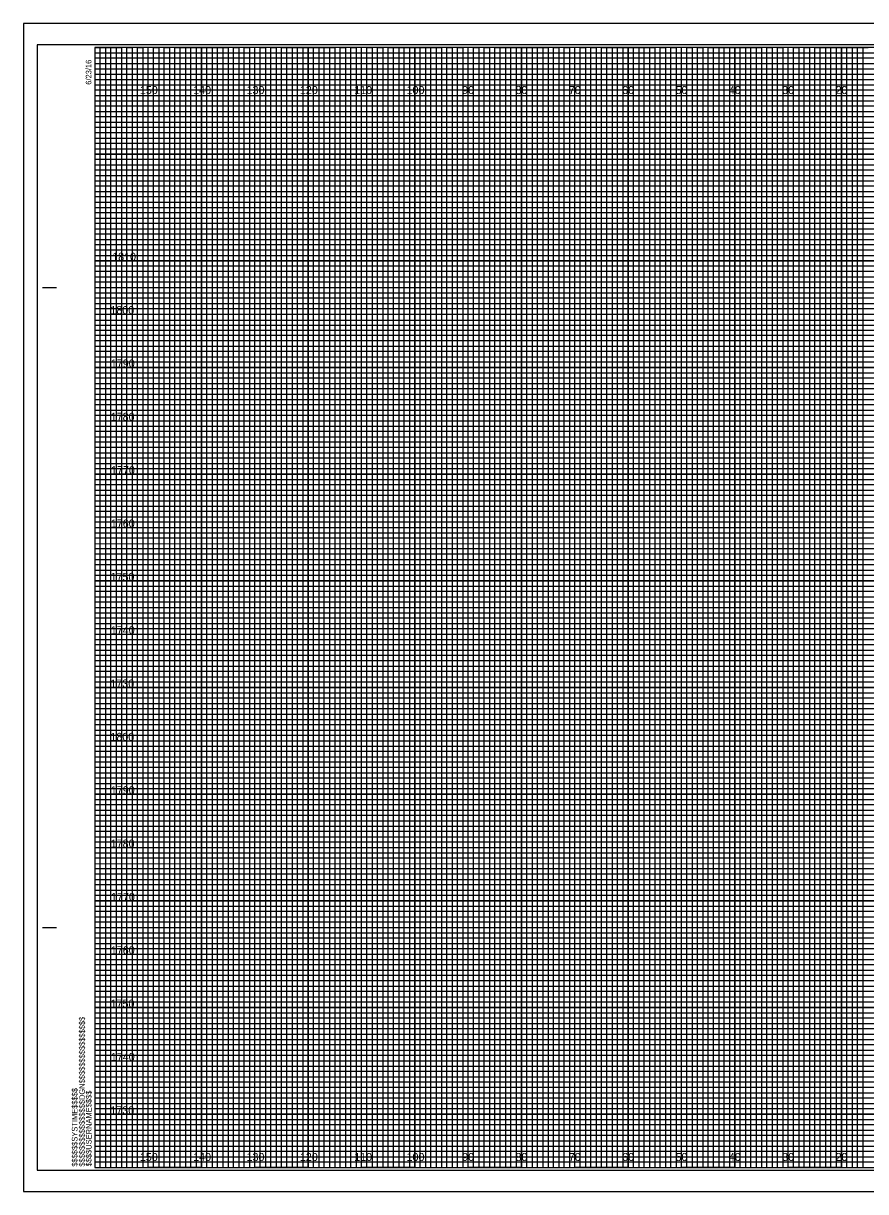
# Model space of a CAD drawing. Extents: x -419 to 4739, y -630 to 13534.
# Drawn here: x 476.2 to 634.1, y 428 to 647 of the extents above; entities that cross this region are included whole.
import ezdxf

# ---------------------------------------------------------------- set-up
doc = ezdxf.new("R2010")
doc.units = 0
for name, color, linetype in [('Old_Level_62', 7, 'Continuous'), ('Pattern 1', 7, 'Continuous'), ('Pattern 18', 7, 'Continuous'), ('Pattern 4', 7, 'Continuous'), ('Pattern 5', 7, 'Continuous'), ('Prop Dimension', 7, 'Continuous'), ('Prop Horizontal Alignment', 7, 'Continuous'), ('Raster_Level_0', 7, 'Continuous'), ('Scratch_Level_0', 7, 'Continuous'), ('Scratch_Level_3', 7, 'Continuous'), ('Scratch_Level_5', 7, 'Continuous')]:
    doc.layers.add(name, color=color, linetype=linetype)

msp = doc.modelspace()

# ---------------------------------------------------------------- linework, layer by layer
at = {"layer": 'Old_Level_62'}
for p, q in [((479.78, 597.54), (482.28, 597.54)), ((479.88, 597.54), (482.38, 597.54)), ((479.78, 477.54), (482.28, 477.54)), ((479.88, 477.54), (482.38, 477.54)), ((489.58, 432.54), (489.58, 432.54)), ((489.58, 432.54), (489.58, 432.54)), ((489.58, 432.54), (489.58, 432.54)), ((489.58, 432.54), (489.58, 432.54)), ((489.58, 432.54), (489.58, 432.54)), ((489.58, 432.54), (489.58, 432.54)), ((489.58, 432.54), (489.58, 432.54))]:
    msp.add_line(p, q, dxfattribs=at)
msp.add_lwpolyline([(809.58, 642.54), (489.58, 642.54), (489.58, 432.54), (809.58, 432.54)], close=True, dxfattribs=at)
at = {"layer": 'Pattern 18'}
msp.add_lwpolyline([(476.18, 428.04), (812.88, 428.04), (812.88, 647.04), (476.18, 647.04)], close=True, dxfattribs=at)
at = {"layer": 'Pattern 4'}
for p, q in [((489.58, 641.54), (749.58, 641.54)), ((749.58, 640.52), (489.58, 640.52)), ((489.58, 640.52), (489.58, 639.54)), ((489.58, 639.54), (749.58, 639.54)), ((749.58, 638.43), (489.58, 638.43)), ((489.58, 638.43), (489.58, 636.54)), ((489.58, 636.54), (809.58, 636.54))]:
    msp.add_line(p, q, dxfattribs=at)
for points in [[(489.58, 635.54), (759.58, 635.54), (809.58, 635.54), (809.58, 634.54), (489.58, 634.54)], [(489.58, 633.54), (809.58, 633.54), (809.58, 631.54), (489.58, 631.54)], [(489.58, 630.54), (809.58, 630.54), (809.58, 629.54), (489.58, 629.52)], [(489.58, 628.54), (809.58, 628.54), (809.58, 626.54), (489.58, 626.54)], [(489.58, 625.54), (809.58, 625.54), (809.58, 624.54), (489.58, 624.54)], [(489.58, 623.54), (809.58, 623.54), (809.58, 621.54), (489.58, 621.54)], [(489.58, 620.54), (809.58, 620.54), (809.58, 619.54), (489.58, 619.54)], [(489.58, 618.54), (809.58, 618.54), (809.58, 616.54), (489.58, 616.54)], [(489.58, 615.54), (809.58, 615.54), (809.58, 614.54), (489.58, 614.54)], [(489.58, 613.54), (809.58, 613.54), (809.58, 611.54), (489.58, 611.54)], [(489.58, 610.54), (809.58, 610.54), (809.58, 609.54), (489.58, 609.54)], [(489.58, 608.54), (809.58, 608.54), (809.58, 606.49), (809.58, 605.54), (809.58, 604.54), (489.58, 604.54)], [(489.58, 606.54), (809.58, 606.54), (809.58, 605.54), (489.58, 605.54)], [(489.58, 603.54), (809.58, 603.54), (809.58, 601.54), (489.58, 601.57)], [(489.58, 601.57), (809.58, 601.54), (809.58, 600.54), (489.58, 600.54)], [(489.58, 599.54), (809.58, 599.54), (809.58, 598.54), (489.58, 598.54)], [(489.58, 596.54), (809.58, 596.54), (809.58, 595.54), (489.58, 595.54)], [(489.58, 594.54), (809.58, 594.54), (809.58, 593.54), (489.58, 593.54)], [(489.51, 591.43), (809.58, 591.43), (809.58, 590.42), (489.51, 590.42)], [(489.58, 589.54), (809.58, 589.54), (809.58, 588.54), (489.58, 588.54)], [(489.58, 586.54), (809.58, 586.54), (809.58, 585.54), (489.58, 585.54)], [(489.58, 584.54), (809.58, 584.54), (809.58, 583.54), (489.58, 583.54)], [(489.58, 581.54), (809.58, 581.54), (809.58, 580.54), (489.58, 580.54)], [(489.58, 579.54), (809.58, 579.54), (809.58, 578.54), (489.58, 578.54)], [(489.58, 576.54), (809.58, 576.54), (809.58, 575.54), (489.58, 575.54)], [(489.58, 574.54), (809.58, 574.54), (809.58, 573.54), (489.58, 573.54)], [(489.58, 571.54), (809.58, 571.54), (809.57, 570.52), (489.58, 570.54)], [(489.58, 569.54), (809.58, 569.54), (809.58, 568.54), (489.58, 568.54)], [(489.58, 566.54), (809.58, 566.54), (809.58, 565.54), (489.58, 565.54)], [(489.58, 564.54), (809.58, 564.54), (809.58, 563.54), (489.58, 563.54)], [(489.58, 561.54), (809.58, 561.54), (809.58, 560.54), (489.58, 560.54)], [(489.58, 559.54), (809.58, 559.54), (809.58, 558.54), (489.58, 558.54)], [(489.58, 556.54), (809.58, 556.54), (809.58, 555.54), (489.58, 555.54)], [(489.58, 554.54), (809.58, 554.54), (809.58, 553.54), (489.58, 553.54)], [(489.58, 551.54), (809.58, 551.54), (809.58, 550.54), (489.58, 550.54)], [(489.58, 549.53), (809.65, 549.45), (809.58, 548.54), (489.58, 548.54)], [(489.58, 546.54), (809.58, 546.54), (809.58, 545.54), (489.58, 545.54)], [(489.58, 544.54), (809.58, 544.54), (809.58, 543.54), (489.58, 543.54)], [(489.58, 541.54), (809.58, 541.54), (809.58, 540.54), (489.58, 540.54)], [(489.58, 539.54), (809.58, 539.54), (809.58, 538.54), (489.58, 538.54)], [(489.58, 536.54), (809.58, 536.54), (809.58, 535.54), (489.58, 535.54)], [(489.58, 534.54), (809.58, 534.54), (809.58, 533.54), (489.58, 533.54)], [(489.58, 531.54), (809.58, 531.54), (809.58, 530.54), (489.58, 530.54)], [(489.58, 529.54), (809.58, 529.54), (809.58, 528.54), (489.58, 528.54)], [(489.58, 526.54), (809.58, 526.54), (809.58, 525.54), (489.58, 525.54)], [(489.58, 524.54), (809.58, 524.54), (809.58, 523.54), (489.58, 523.54)], [(489.58, 521.54), (809.58, 521.54), (809.58, 520.54), (489.58, 520.54)], [(489.58, 519.54), (809.58, 519.54), (809.58, 518.54), (489.58, 518.54)], [(489.58, 516.54), (809.58, 516.54), (809.58, 515.54), (489.58, 515.54)], [(489.58, 514.54), (809.58, 514.54), (809.58, 513.54), (489.58, 513.54)], [(489.58, 511.54), (809.58, 511.54), (809.57, 510.52), (489.58, 510.54)], [(489.58, 509.54), (809.58, 509.54), (809.58, 508.54), (489.58, 508.54)], [(489.58, 506.54), (809.58, 506.54), (809.58, 505.54), (489.58, 505.54)], [(489.58, 504.54), (809.58, 504.54), (809.58, 503.54), (489.58, 503.54)], [(489.58, 501.54), (809.58, 501.54), (809.58, 500.54), (489.58, 500.54)], [(489.58, 499.54), (809.58, 499.54), (809.58, 498.54), (489.58, 498.54)], [(489.58, 496.54), (809.58, 496.54), (809.58, 495.54), (489.58, 495.54)], [(489.58, 494.54), (809.58, 494.54), (809.58, 493.54), (489.58, 493.54)], [(489.58, 491.54), (809.58, 491.54), (809.58, 490.54), (489.58, 490.54)], [(489.58, 489.53), (809.65, 489.45), (809.58, 488.54), (489.58, 488.54)], [(489.58, 486.54), (809.58, 486.54), (809.58, 485.54), (489.58, 485.54)], [(489.58, 484.54), (809.58, 484.54), (809.58, 483.54), (489.58, 483.54)], [(489.58, 481.54), (809.58, 481.54), (809.58, 480.54), (489.58, 480.54)], [(489.58, 479.54), (809.58, 479.54), (809.58, 478.54), (489.58, 478.54)], [(489.58, 476.54), (809.58, 476.54), (809.58, 475.54), (489.58, 475.54)], [(489.58, 474.54), (809.58, 474.54), (809.58, 473.54), (489.58, 473.54)], [(489.58, 471.54), (809.58, 471.54), (809.58, 470.54), (489.58, 470.54)], [(489.58, 469.54), (809.58, 469.54), (809.58, 468.54), (489.58, 468.54)], [(489.58, 466.54), (809.58, 466.54), (809.58, 465.54), (489.58, 465.54)], [(489.58, 464.54), (809.58, 464.54), (809.58, 463.54), (489.58, 463.54)], [(489.58, 461.54), (809.58, 461.54), (809.58, 460.54), (489.58, 460.54)], [(489.58, 459.54), (809.58, 459.54), (809.58, 458.54), (489.58, 458.54)], [(489.58, 456.54), (809.58, 456.54), (809.58, 455.54), (489.58, 455.54)], [(489.58, 454.54), (809.58, 454.54), (809.58, 453.54), (489.58, 453.54)], [(489.58, 451.54), (809.58, 451.54), (809.58, 450.54), (489.58, 450.54)], [(489.58, 449.54), (809.58, 449.54), (809.58, 448.54), (489.58, 448.54)], [(489.58, 446.54), (809.58, 446.54), (809.58, 445.54), (489.58, 445.54)], [(489.58, 444.54), (809.58, 444.54), (809.58, 443.54), (489.58, 443.54)], [(489.58, 441.54), (809.58, 441.54), (809.58, 440.54), (489.58, 440.54)], [(489.58, 439.54), (809.58, 439.54), (809.58, 438.54), (489.58, 438.54)], [(489.58, 436.54), (809.58, 436.54), (809.58, 435.54), (489.58, 435.54)], [(489.58, 434.54), (809.58, 434.54), (809.58, 433.54), (489.58, 433.54)]]:
    msp.add_lwpolyline(points, dxfattribs=at)
at = {"layer": 'Pattern 5'}
for p, q in [((812.88, 647.04), (476.18, 647.04)), ((476.18, 647.04), (476.18, 428.04)), ((476.18, 428.04), (812.88, 428.04))]:
    msp.add_line(p, q, dxfattribs=at)
at = {"layer": 'Prop Dimension'}
for points in [[(489.58, 432.54), (490.58, 432.54), (490.58, 642.54), (491.58, 642.54), (491.58, 432.54)], [(491.58, 432.54), (492.58, 432.54), (492.58, 642.54), (493.58, 642.54), (493.58, 432.54)], [(494.58, 432.54), (495.58, 432.54), (495.58, 642.54), (496.58, 642.54), (496.58, 432.54)], [(496.58, 432.54), (497.58, 432.54), (497.58, 642.54), (498.58, 642.54), (498.58, 432.54)], [(499.58, 432.54), (500.58, 432.54), (500.58, 642.54), (501.58, 642.54), (501.58, 432.54)], [(501.58, 432.54), (502.58, 432.54), (502.58, 642.54), (503.58, 642.54), (503.58, 432.54)], [(504.58, 432.54), (505.58, 432.54), (505.58, 642.54), (506.58, 642.54), (506.58, 432.54)], [(506.58, 432.54), (507.58, 432.54), (507.58, 642.54), (508.58, 642.54), (508.58, 432.54)], [(509.58, 432.54), (510.58, 432.54), (510.58, 642.54), (511.58, 642.54), (511.58, 432.54)], [(511.58, 432.54), (512.58, 432.54), (512.58, 642.54), (513.58, 642.54), (513.58, 432.54)], [(514.58, 432.54), (515.58, 432.54), (515.58, 642.54), (516.58, 642.54), (516.58, 432.54)], [(516.58, 432.54), (517.58, 432.54), (517.58, 642.54), (518.58, 642.54), (518.58, 432.54)], [(519.58, 432.54), (520.58, 432.54), (520.58, 642.54), (521.58, 642.54), (521.58, 432.54)], [(521.58, 432.54), (522.58, 432.54), (522.58, 642.54), (523.58, 642.54), (523.58, 432.54)], [(524.58, 432.54), (525.58, 432.54), (525.58, 642.54), (526.58, 642.54), (526.58, 432.54)], [(526.58, 432.54), (527.58, 432.54), (527.58, 642.54), (528.58, 642.54), (528.58, 432.54)], [(529.58, 432.54), (530.58, 432.54), (530.58, 642.54), (531.58, 642.54), (531.58, 432.54)], [(531.58, 432.54), (532.58, 432.54), (532.58, 642.54), (533.58, 642.54), (533.58, 432.54)], [(534.58, 432.54), (535.58, 432.54), (535.58, 642.54), (536.58, 642.54), (536.58, 432.54)], [(536.58, 432.54), (537.58, 432.54), (537.58, 642.54), (538.58, 642.54), (538.58, 432.54)], [(539.58, 432.54), (540.58, 432.54), (540.58, 642.54), (541.58, 642.54), (541.58, 432.54)], [(541.58, 432.54), (542.58, 432.54), (542.58, 642.54), (543.58, 642.54), (543.58, 432.54)], [(544.58, 432.54), (545.58, 432.54), (545.58, 642.54), (546.58, 642.54), (546.58, 432.54)], [(546.58, 432.54), (547.58, 432.54), (547.58, 642.54), (548.58, 642.54), (548.58, 432.54)], [(549.58, 432.54), (550.58, 432.54), (550.58, 642.54), (551.58, 642.54), (551.58, 432.54)], [(551.58, 432.54), (552.58, 432.54), (552.58, 642.54), (553.58, 642.54), (553.58, 432.54)], [(554.58, 432.54), (555.58, 432.54), (555.58, 642.54), (556.58, 642.54), (556.58, 432.54)], [(556.58, 432.54), (557.58, 432.54), (557.58, 642.54), (558.58, 642.54), (558.58, 432.54)], [(559.58, 432.54), (560.58, 432.54), (560.58, 642.54), (561.58, 642.54), (561.58, 432.54)], [(561.58, 432.54), (562.58, 432.54), (562.58, 642.54), (563.58, 642.54), (563.58, 432.54)], [(564.58, 432.54), (565.58, 432.54), (565.58, 642.54), (566.58, 642.54), (566.58, 432.54)], [(566.58, 432.54), (567.58, 432.54), (567.58, 642.54), (568.58, 642.54), (568.58, 432.54)], [(569.58, 432.54), (570.58, 432.54), (570.58, 642.54), (571.58, 642.54), (571.58, 432.54)], [(571.58, 432.54), (572.58, 432.54), (572.58, 642.54), (573.58, 642.54), (573.58, 432.54)], [(574.58, 432.54), (575.58, 432.54), (575.58, 642.54), (576.58, 642.54), (576.58, 432.54)], [(576.58, 432.54), (577.58, 432.54), (577.58, 642.54), (578.58, 642.54), (578.58, 432.54)], [(579.58, 432.54), (580.58, 432.54), (580.58, 642.54), (581.58, 642.54), (581.58, 432.54)], [(581.58, 432.54), (582.58, 432.54), (582.58, 642.54), (583.58, 642.54), (583.58, 432.54)], [(584.58, 432.54), (585.58, 432.54), (585.58, 642.54), (586.58, 642.54), (586.58, 432.54)], [(586.58, 432.54), (587.58, 432.54), (587.58, 642.54), (588.58, 642.54), (588.58, 432.54)], [(589.58, 432.54), (590.58, 432.54), (590.58, 642.54), (591.58, 642.54), (591.58, 432.54)], [(591.58, 432.54), (592.58, 432.54), (592.58, 642.54), (593.58, 642.54), (593.58, 432.54)], [(594.58, 432.54), (595.58, 432.54), (595.58, 642.54), (596.58, 642.54), (596.58, 432.54)], [(596.58, 432.54), (597.58, 432.54), (597.58, 642.54), (598.58, 642.54), (598.58, 432.54)], [(599.58, 432.54), (600.58, 432.54), (600.58, 642.54), (601.58, 642.54), (601.58, 432.54)], [(601.58, 432.54), (602.58, 432.54), (602.58, 642.54), (603.58, 642.54), (603.58, 432.54)], [(604.58, 432.54), (605.58, 432.54), (605.58, 642.54), (606.58, 642.54), (606.58, 432.54)], [(606.58, 432.54), (607.58, 432.54), (607.58, 642.54), (608.58, 642.54), (608.58, 432.54)], [(609.58, 432.54), (610.58, 432.54), (610.58, 642.54), (611.58, 642.54), (611.58, 432.54)], [(611.58, 432.54), (612.58, 432.54), (612.58, 642.54), (613.58, 642.54), (613.58, 432.54)], [(614.58, 432.54), (615.58, 432.54), (615.58, 642.54), (616.58, 642.54), (616.58, 432.54)], [(616.58, 432.54), (617.58, 432.54), (617.58, 642.54), (618.58, 642.54), (618.58, 432.54)], [(619.58, 432.54), (620.58, 432.54), (620.58, 642.54), (621.58, 642.54), (621.58, 432.54)], [(621.58, 432.54), (622.58, 432.54), (622.58, 642.54), (623.58, 642.54), (623.58, 432.54)], [(624.58, 432.54), (625.58, 432.54), (625.58, 642.54), (626.58, 642.54), (626.58, 432.54)], [(626.58, 432.54), (627.58, 432.54), (627.58, 642.54), (628.58, 642.54), (628.58, 432.54)], [(629.58, 432.54), (630.58, 432.54), (630.58, 642.54), (631.58, 642.54), (631.58, 432.54)], [(631.58, 432.54), (632.58, 432.54), (632.58, 642.54), (633.58, 642.54), (633.58, 432.54)]]:
    msp.add_lwpolyline(points, dxfattribs=at)
at = {"layer": 'Prop Horizontal Alignment'}
for points in [[(489.58, 642.54), (494.58, 642.54), (494.58, 432.54), (504.58, 432.54), (504.58, 642.54), (514.58, 642.54), (514.58, 432.54), (524.58, 432.54), (524.58, 642.54), (534.58, 642.54), (534.58, 432.54), (544.58, 432.54), (544.58, 642.54), (554.58, 642.54), (554.58, 432.54), (564.58, 432.54), (564.58, 642.54), (574.58, 642.54), (574.58, 432.54), (584.58, 432.54), (584.58, 642.54), (594.58, 642.54), (594.58, 432.54), (604.58, 432.54), (604.58, 642.54), (614.58, 642.54), (614.58, 432.54), (624.58, 432.54), (624.58, 642.54), (634.58, 642.54)], [(489.58, 637.54), (764.58, 637.54)], [(489.58, 617.54), (809.58, 617.54), (809.58, 627.54), (489.58, 627.54)], [(489.58, 597.54), (809.58, 597.54), (809.58, 607.54), (489.58, 607.54)], [(489.58, 577.54), (809.58, 577.54), (809.58, 587.54), (489.58, 587.54)], [(489.58, 557.54), (809.58, 557.54), (809.58, 567.54), (489.58, 567.54)], [(489.58, 537.54), (809.58, 537.54), (809.58, 547.54), (489.58, 547.54)], [(489.58, 517.54), (809.58, 517.54), (809.58, 527.54), (489.58, 527.54)], [(489.58, 497.54), (809.58, 497.54), (809.58, 507.54), (489.58, 507.54)], [(489.58, 477.54), (809.58, 477.54), (809.58, 487.54), (489.58, 487.54)], [(489.58, 457.54), (809.58, 457.54), (809.58, 467.54), (489.58, 467.54)], [(489.58, 437.54), (809.58, 437.54), (809.58, 447.54), (489.58, 447.54)]]:
    msp.add_lwpolyline(points, dxfattribs=at)
at = {"layer": 'Scratch_Level_0'}
for p, q in [((499.58, 432.54), (499.58, 642.54)), ((509.58, 432.54), (509.58, 642.54)), ((519.58, 432.54), (519.58, 642.54)), ((529.58, 432.54), (529.58, 642.54)), ((539.58, 432.54), (539.58, 642.54)), ((549.58, 432.54), (549.58, 642.54)), ((559.58, 432.54), (559.58, 642.54)), ((569.58, 432.54), (569.58, 642.54)), ((579.58, 432.54), (579.58, 642.54)), ((589.58, 432.54), (589.58, 642.54)), ((599.58, 432.54), (599.58, 642.54)), ((609.58, 432.54), (609.58, 642.54)), ((619.58, 432.54), (619.58, 642.54)), ((629.58, 432.54), (629.58, 642.54)), ((489.58, 632.54), (809.58, 632.54)), ((489.58, 622.54), (809.58, 622.54)), ((489.58, 612.54), (809.58, 612.54)), ((489.58, 602.54), (809.58, 602.54)), ((489.58, 592.54), (809.58, 592.54)), ((489.58, 582.54), (809.58, 582.54)), ((489.58, 572.54), (809.58, 572.54)), ((489.58, 562.54), (809.58, 562.54)), ((489.58, 552.54), (809.58, 552.54)), ((489.58, 542.54), (809.58, 542.54)), ((489.58, 532.54), (809.58, 532.54)), ((489.58, 522.54), (809.58, 522.54)), ((489.58, 512.54), (809.58, 512.54)), ((489.58, 502.54), (809.58, 502.54)), ((489.58, 492.54), (809.58, 492.54)), ((489.58, 482.54), (809.58, 482.54)), ((489.58, 472.54), (809.58, 472.54)), ((489.58, 462.54), (809.58, 462.54)), ((489.58, 452.54), (809.58, 452.54)), ((489.58, 442.54), (809.58, 442.54))]:
    msp.add_line(p, q, dxfattribs=at)
at = {"layer": 'Scratch_Level_3'}
for p, q in [((499.58, 642.54), (489.58, 642.54)), ((499.58, 432.54), (499.58, 642.54)), ((519.58, 642.54), (509.58, 642.54)), ((509.58, 642.54), (509.58, 432.54)), ((519.58, 432.54), (519.58, 642.54)), ((539.58, 642.54), (529.58, 642.54)), ((529.58, 642.54), (529.58, 432.54)), ((539.58, 432.54), (539.58, 642.54)), ((559.58, 642.54), (549.58, 642.54)), ((549.58, 642.54), (549.58, 432.54)), ((559.58, 432.54), (559.58, 642.54)), ((579.58, 642.54), (569.58, 642.54)), ((569.58, 642.54), (569.58, 432.54)), ((579.58, 432.54), (579.58, 642.54)), ((599.58, 642.54), (589.58, 642.54)), ((589.58, 642.54), (589.58, 432.54)), ((599.58, 432.54), (599.58, 642.54)), ((619.58, 642.54), (609.58, 642.54)), ((609.58, 642.54), (609.58, 432.54)), ((619.58, 432.54), (619.58, 642.54)), ((639.58, 642.54), (629.58, 642.54)), ((629.58, 642.54), (629.58, 432.54)), ((509.58, 432.54), (499.58, 432.54)), ((529.58, 432.54), (519.58, 432.54)), ((549.58, 432.54), (539.58, 432.54)), ((569.58, 432.54), (559.58, 432.54)), ((589.58, 432.54), (579.58, 432.54)), ((609.58, 432.54), (599.58, 432.54)), ((629.58, 432.54), (619.58, 432.54))]:
    msp.add_line(p, q, dxfattribs=at)
for points in [[(489.58, 632.54), (809.58, 632.54), (809.58, 622.54), (489.58, 622.54)], [(489.58, 612.54), (809.58, 612.54), (809.58, 602.54), (489.58, 602.54)], [(489.58, 592.54), (809.58, 592.54), (809.58, 582.54), (489.58, 582.54)], [(489.58, 572.54), (809.58, 572.54), (809.58, 562.54), (489.58, 562.54)], [(489.58, 552.54), (809.58, 552.54), (809.58, 542.54), (489.58, 542.54)], [(489.58, 532.54), (809.58, 532.54), (809.58, 522.54), (489.58, 522.54)], [(489.58, 512.54), (809.58, 512.54), (809.58, 502.54), (489.58, 502.54)], [(489.58, 492.54), (809.58, 492.54), (809.58, 482.54), (489.58, 482.54)], [(489.58, 472.54), (809.58, 472.54), (809.58, 462.54), (489.58, 462.54)], [(489.58, 452.54), (809.58, 452.54), (809.58, 442.54), (489.58, 442.54)]]:
    msp.add_lwpolyline(points, dxfattribs=at)
at = {"layer": 'Scratch_Level_5'}
msp.add_lwpolyline([(478.78, 432.04), (811.98, 432.04), (811.98, 643.04), (478.78, 643.04)], close=True, dxfattribs=at)

# ---------------------------------------------------------------- texts
at = {"layer": 'Old_Level_62'}
for s, p in [('6/23/16', (488.93, 635.54)), ('$$$$$$$$$$$$$$$$DGN$$$$$$$$$$$$$$$$', (487.7, 432.72)), ('$$$$$$SYSTIME$$$$$', (486.32, 432.72)), ('$$$$USERNAME$$$$', (488.96, 432.77))]:
    msp.add_text(s, height=1.05, rotation=90, dxfattribs=at).set_placement(p)
at = {"layer": 'Pattern 1'}
for s, p in [('1810', (492.83, 602.54)), ('1800', (492.5, 592.54)), ('1790', (492.58, 582.54)), ('1780', (492.56, 572.54)), ('1770', (492.62, 562.54)), ('1760', (492.58, 552.54)), ('1750', (492.53, 542.54)), ('1740', (492.58, 532.54)), ('1730', (492.5, 522.54)), ('1800', (492.5, 512.54)), ('1790', (492.58, 502.54)), ('1780', (492.56, 492.54)), ('1770', (492.62, 482.54)), ('1760', (492.58, 472.54)), ('1750', (492.53, 462.54)), ('1740', (492.58, 452.54)), ('1730', (492.5, 442.54))]:
    msp.add_text(s, height=1.5, dxfattribs=at).set_placement(p)
at = {"layer": 'Raster_Level_0'}
for s, p in [('150', (498.02, 633.79)), ('140', (508.02, 633.79)), ('130', (518.02, 633.79)), ('120', (528.02, 633.79)), ('110', (538.2, 633.79)), ('100', (548.02, 633.79)), ('90', (558.44, 633.79)), ('80', (568.44, 633.79)), ('70', (578.44, 633.79)), ('60', (588.44, 633.79)), ('50', (598.44, 633.79)), ('40', (608.44, 633.79)), ('30', (618.44, 633.79)), ('20', (628.44, 633.79)), ('150', (498.02, 433.79)), ('140', (508.02, 433.79)), ('130', (518.02, 433.79)), ('120', (528.02, 433.79)), ('110', (538.2, 433.79)), ('100', (548.02, 433.79)), ('90', (558.44, 433.79)), ('80', (568.44, 433.79)), ('70', (578.44, 433.79)), ('60', (588.44, 433.79)), ('50', (598.44, 433.79)), ('40', (608.44, 433.79)), ('30', (618.44, 433.79)), ('20', (628.44, 433.79))]:
    msp.add_text(s, height=1.5, dxfattribs=at).set_placement(p)

doc.saveas('drawing.dxf')
